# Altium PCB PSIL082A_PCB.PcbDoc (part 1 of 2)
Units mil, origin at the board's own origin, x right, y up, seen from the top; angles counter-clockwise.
Board outline 3500 x 2700 mil, 4 copper layers (Top Layer, Signal Layer 1, Signal Layer 2, Bottom Layer), stack 61.2 mil thick; 62 components, 57 nets, 283 pads, 94 vias.
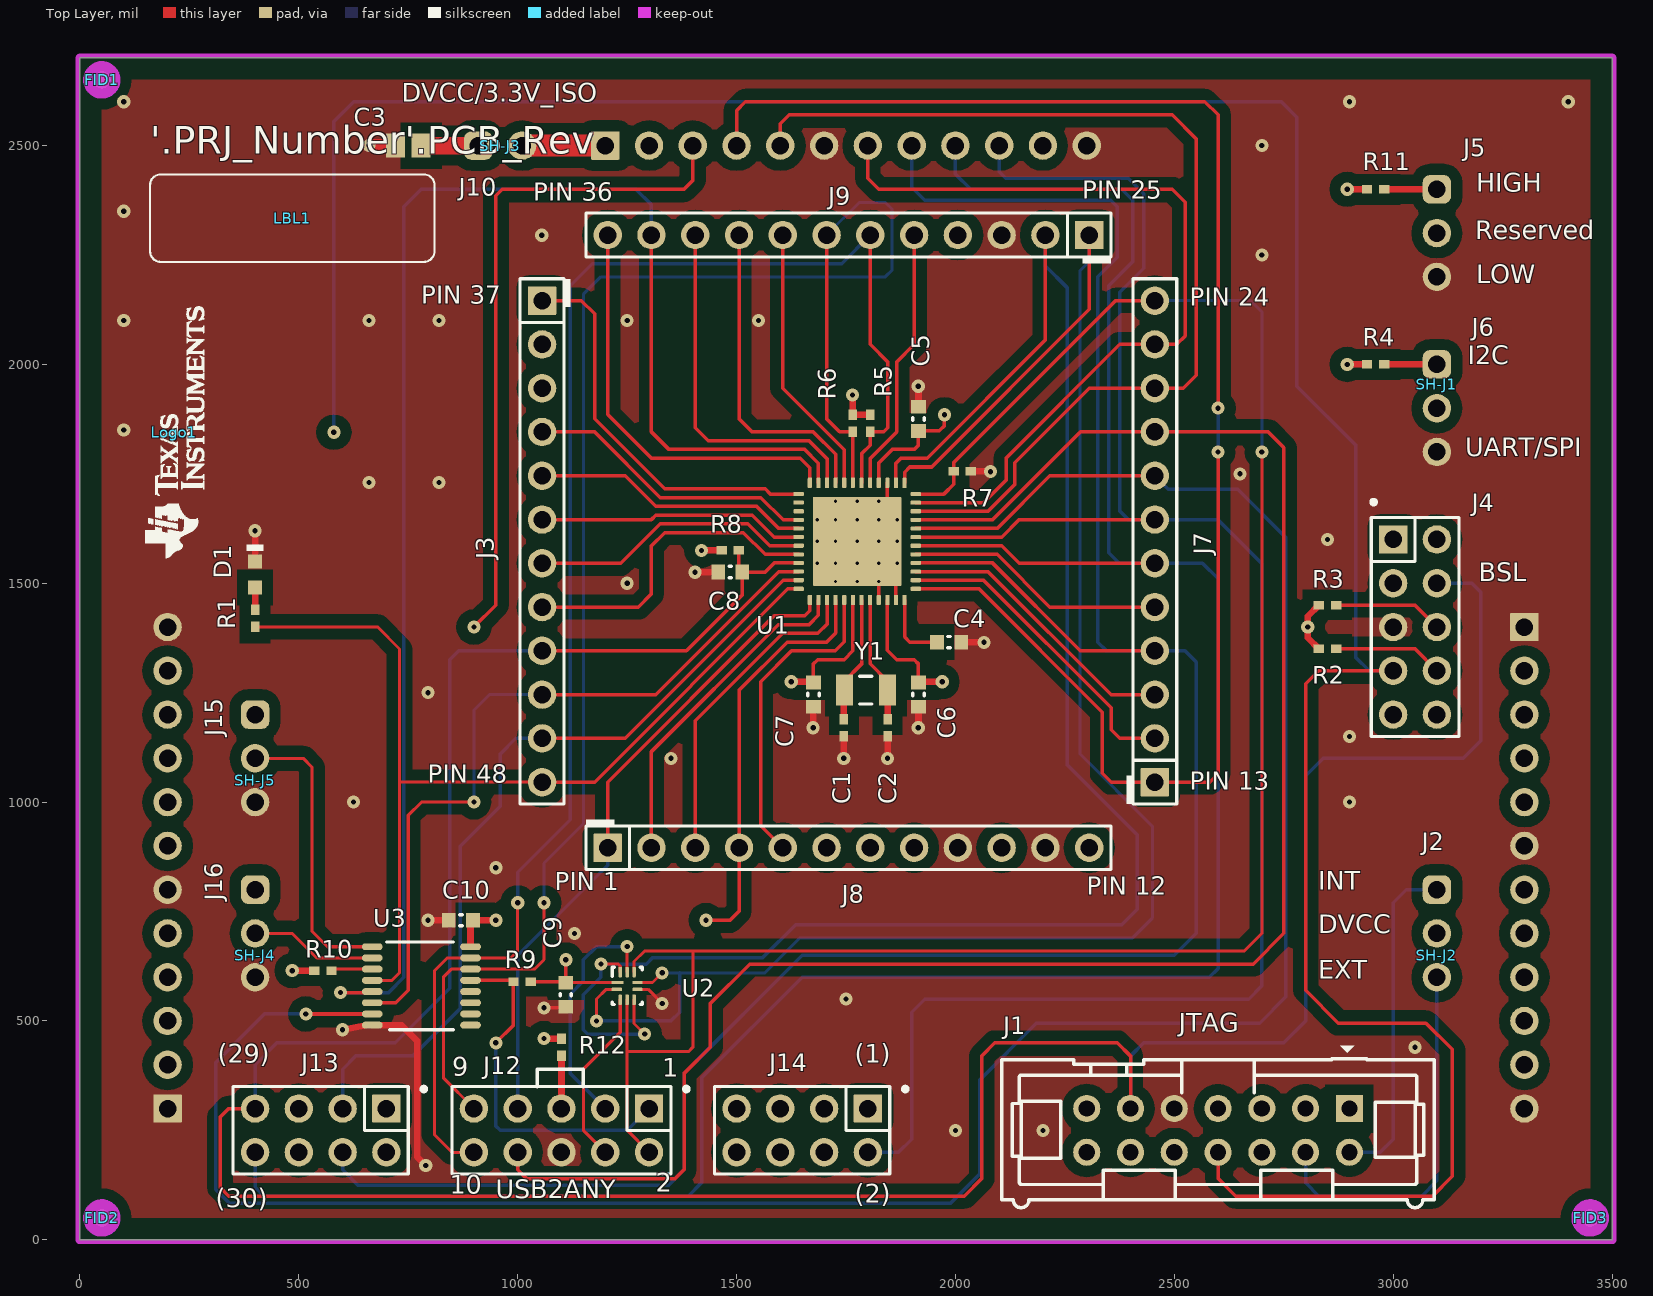
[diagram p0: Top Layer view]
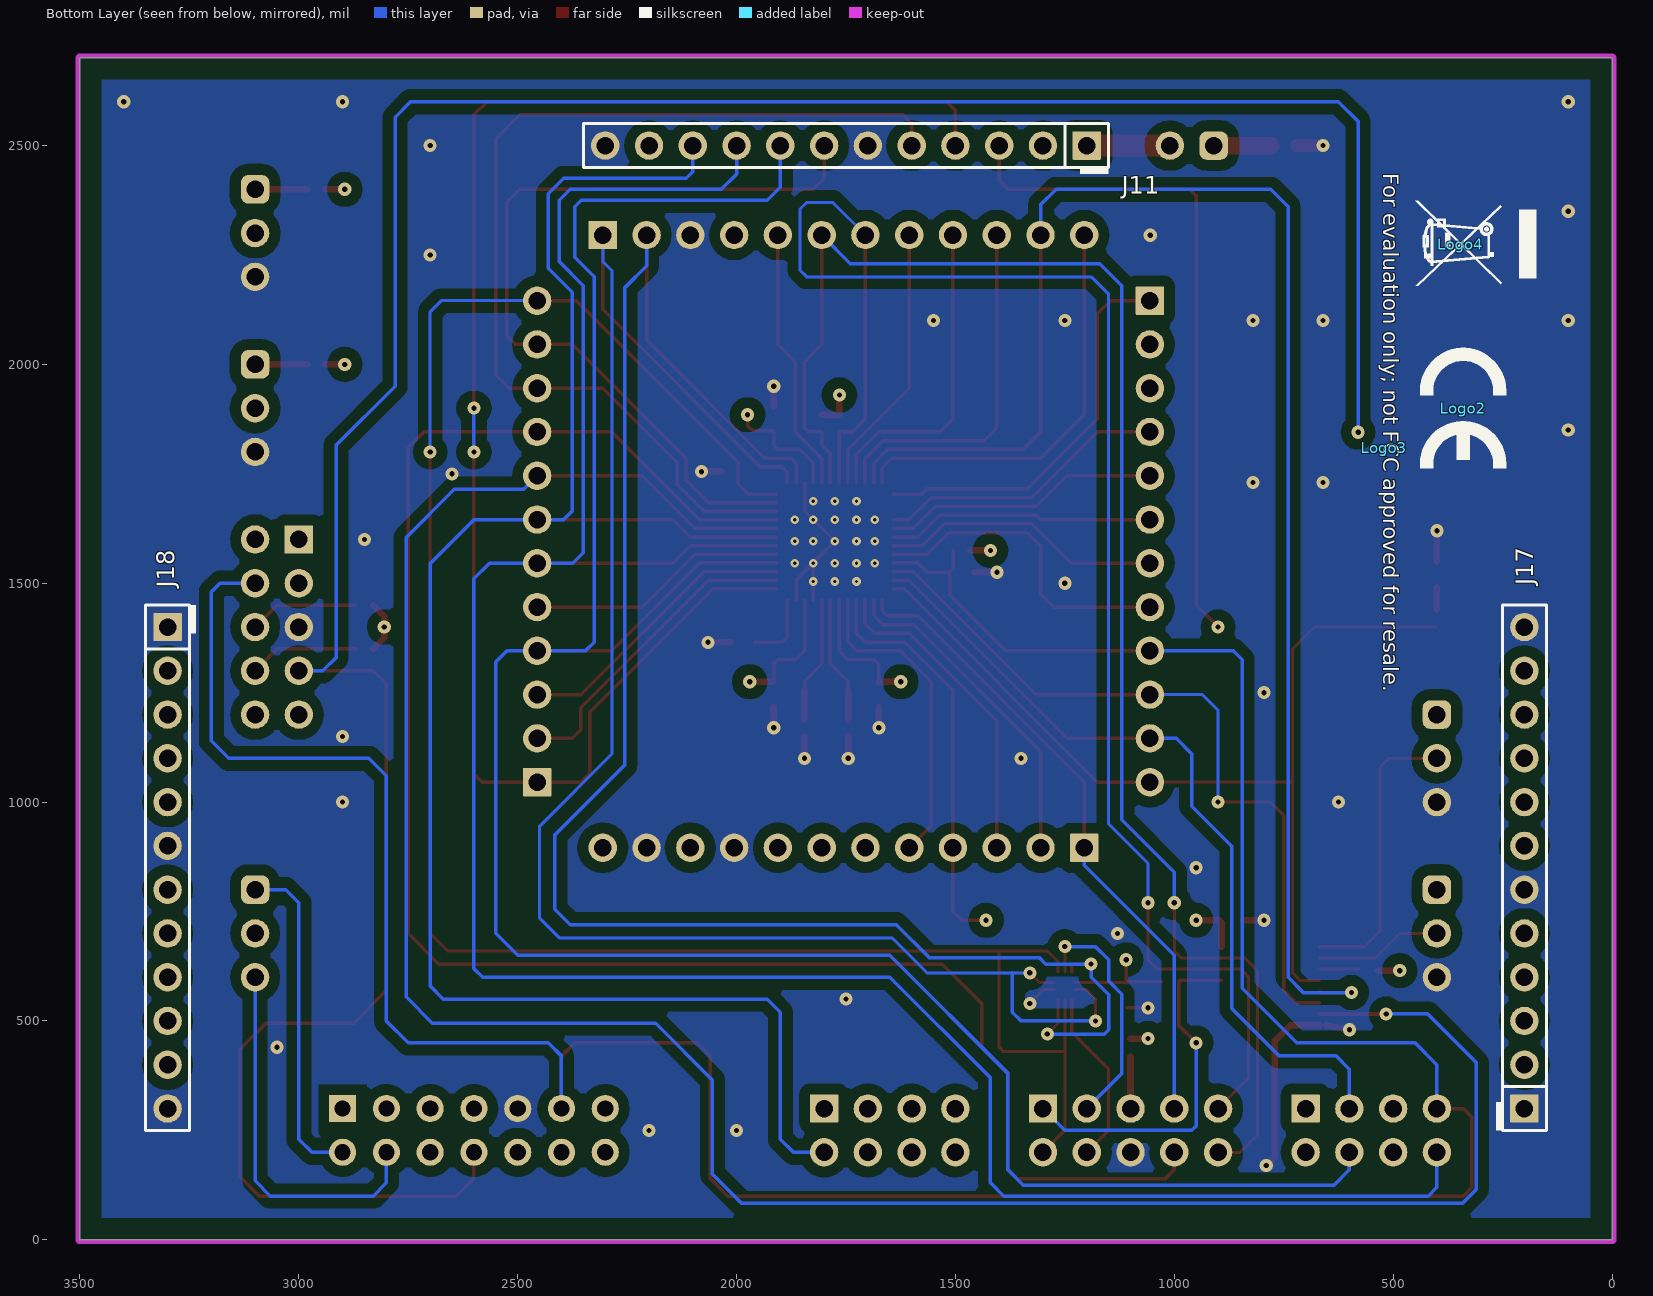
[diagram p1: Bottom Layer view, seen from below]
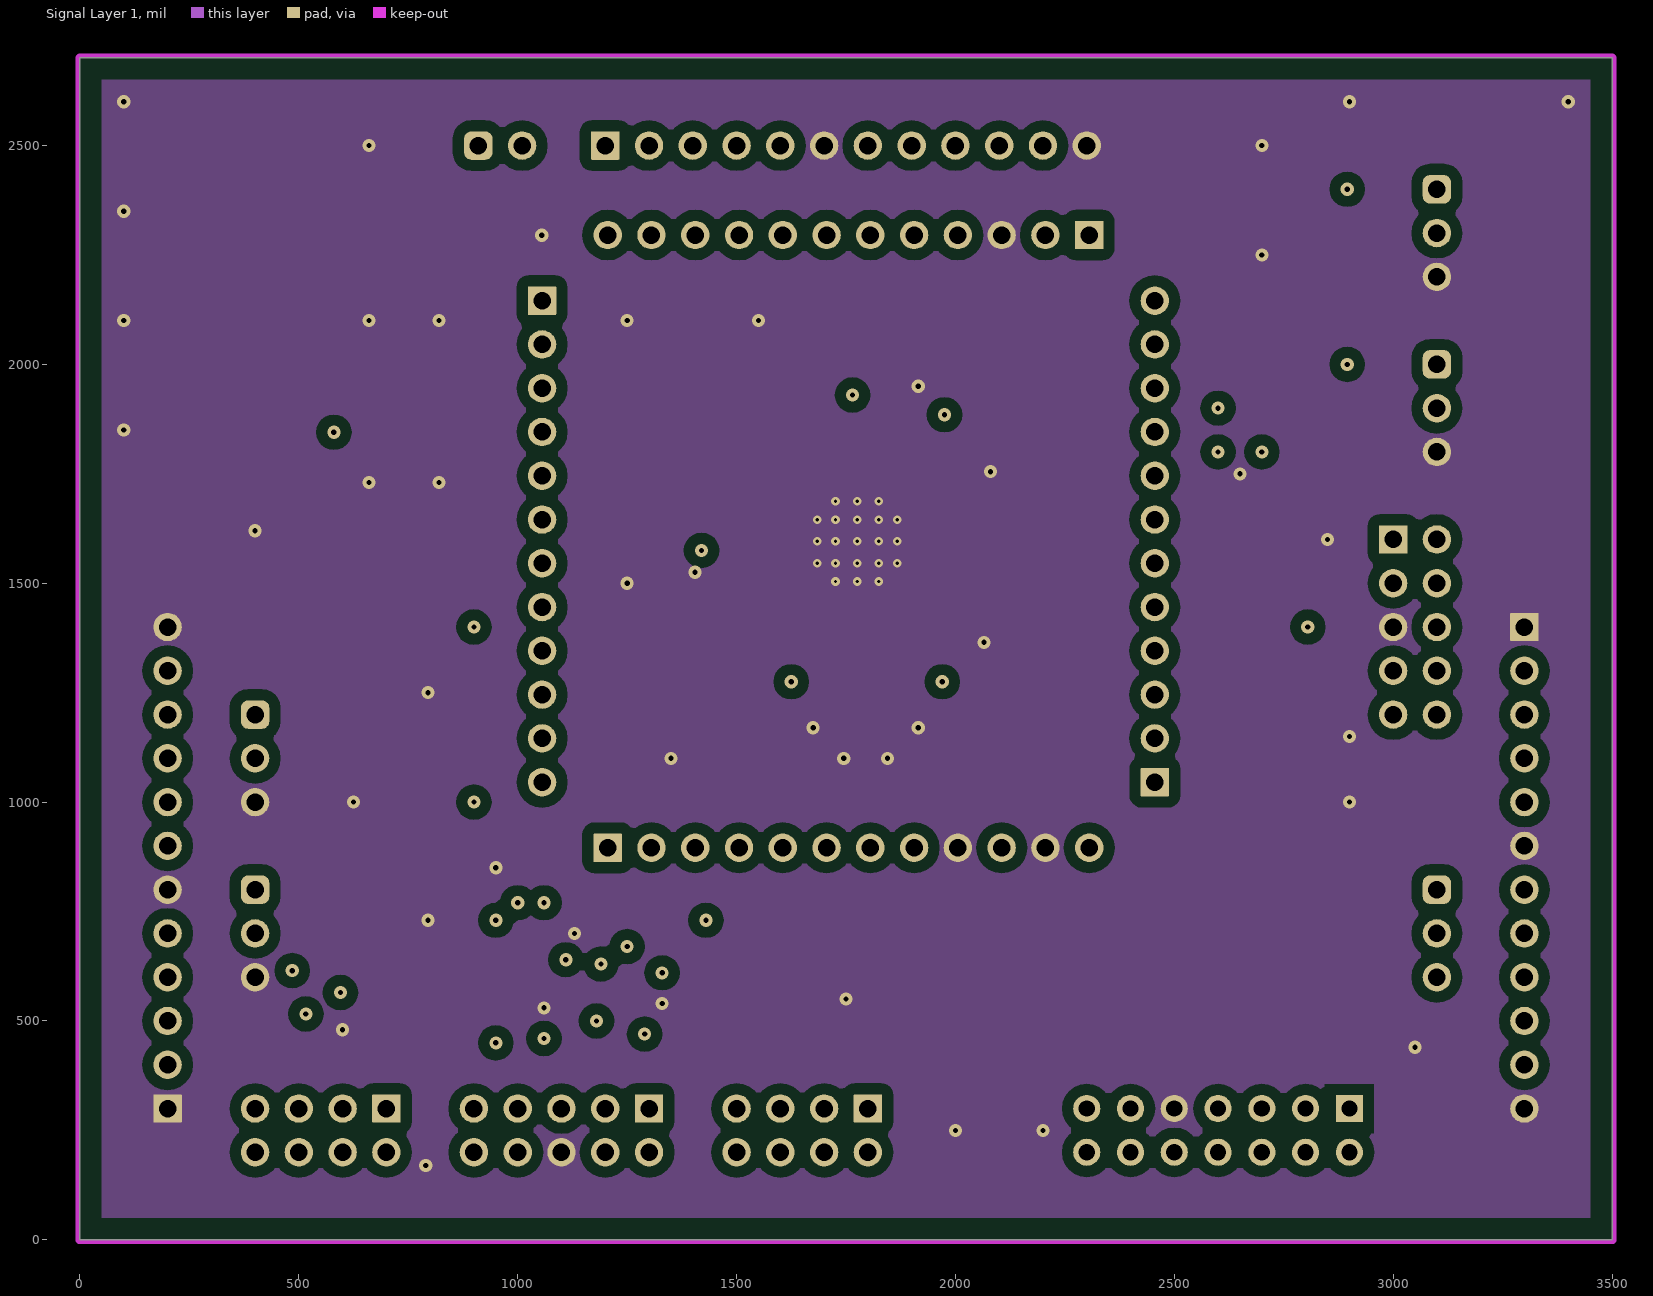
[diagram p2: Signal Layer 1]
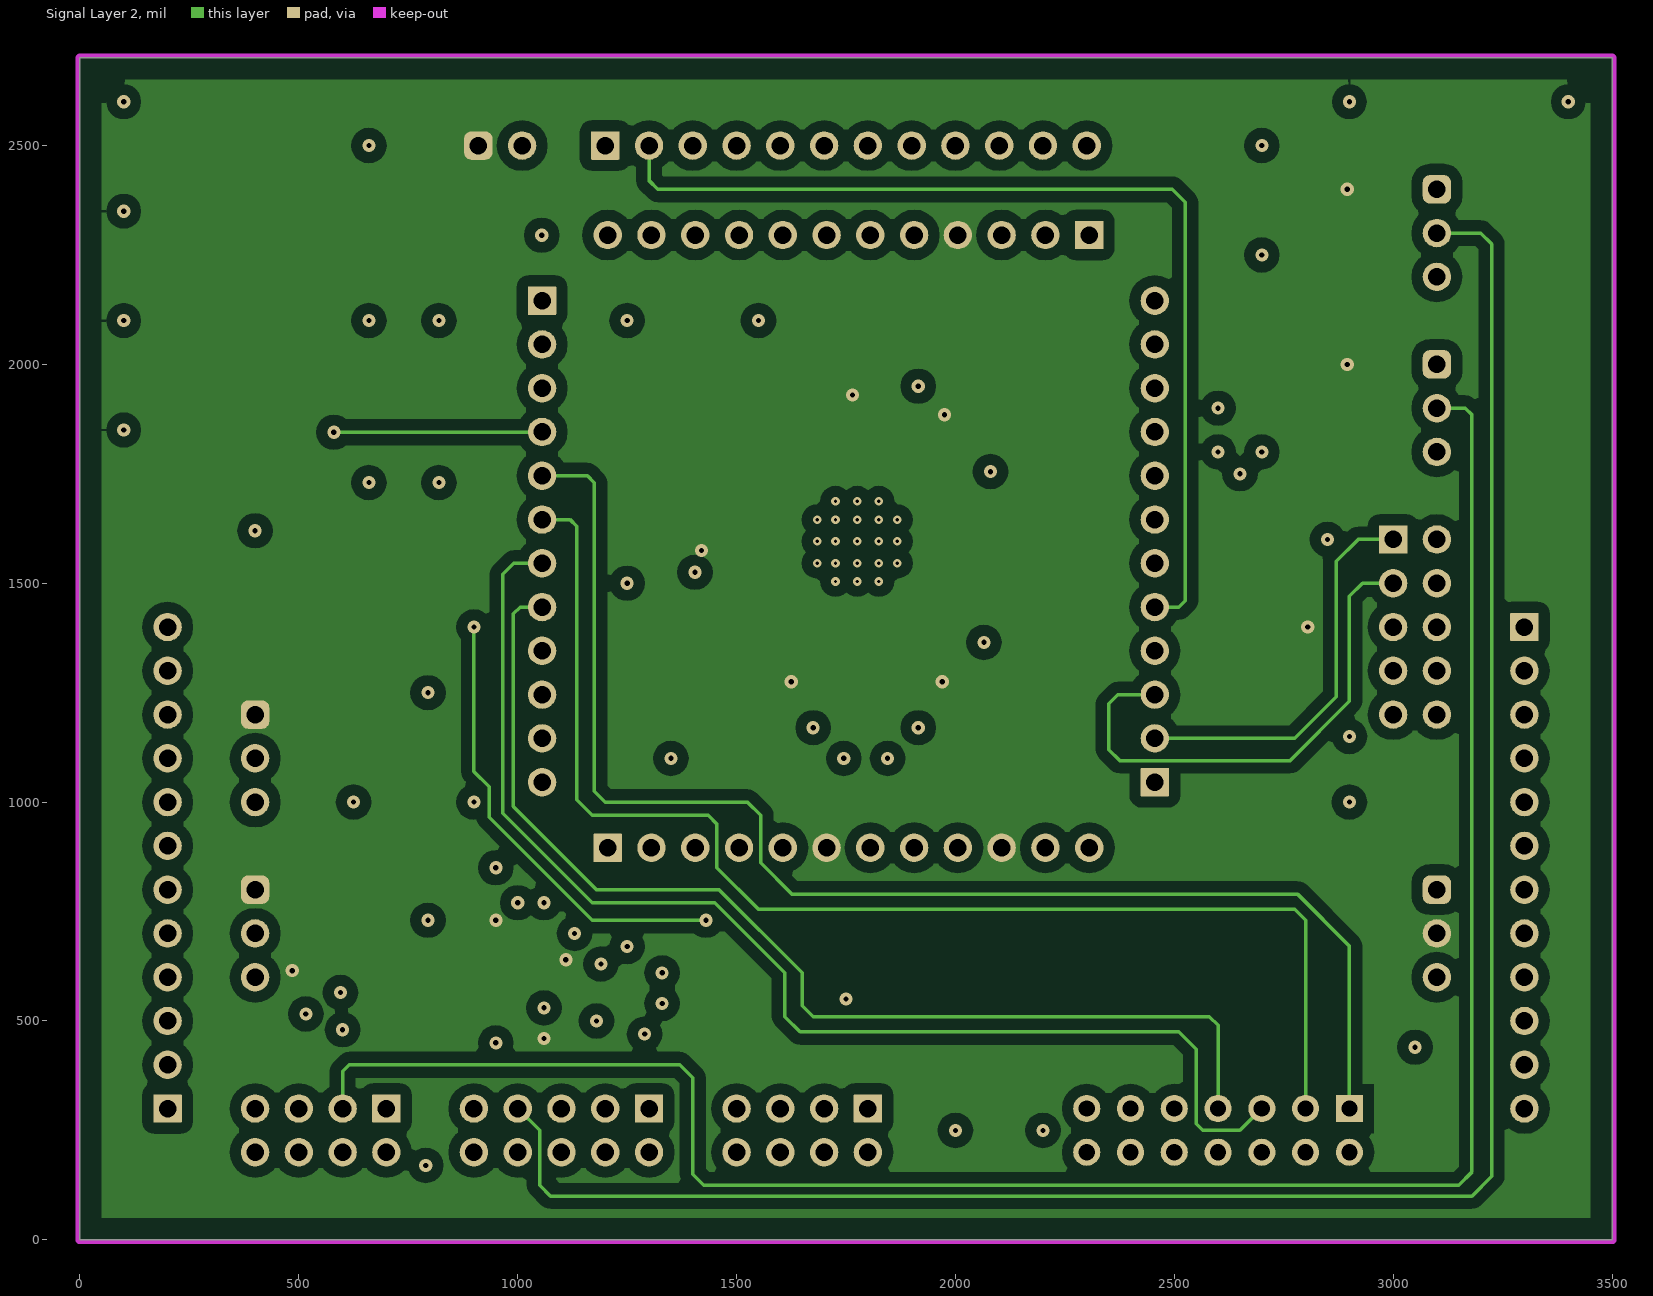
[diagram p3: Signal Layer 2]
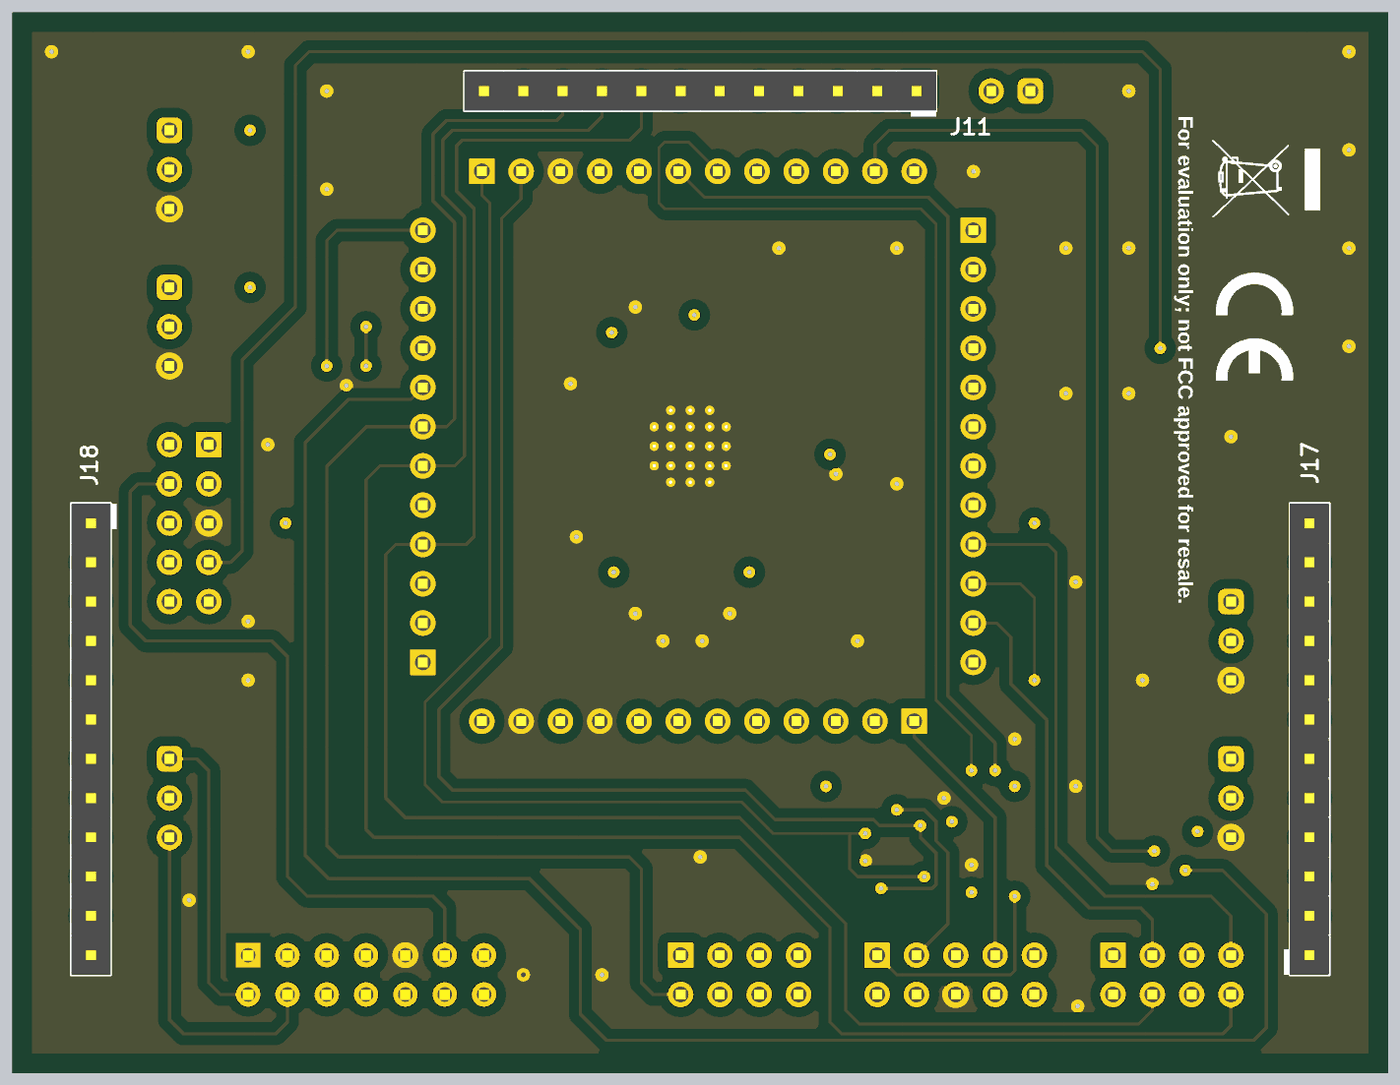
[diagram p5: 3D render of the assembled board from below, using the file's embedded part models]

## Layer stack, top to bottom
Top Solder: solder mask 0.4, Solder Resist, Dk 3.5
Top Layer: signal copper 1.4
Dielectric 2: core 20, FR-4, Dk 4.2
Signal Layer 1: signal copper 1.4
Dielectric1: prepreg 15.6, FR-4, Dk 4.2
Signal Layer 2: signal copper 1.4
Dielectric 3: core 20, FR-4, Dk 4.2
Bottom Layer: signal copper 1.4
Bottom Solder: solder mask 0.4, Solder Resist, Dk 3.5

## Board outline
0,0 3500,0 3500,2700 0,2700

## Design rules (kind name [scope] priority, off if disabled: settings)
AcuteAngle [All] p1: minimum=4.50000000000000E+0001 checktracksonly=FALSE
AssemblyTestPointUsage [All] p1: valid=2
BoardOutlineClearance BoardOutlineClearance_MountingHoles [OnCopper and InComponentClass('Mounting Holes')] p1: gap=40 ignorepadtopadclearanceinfootprint=FALSE
BoardOutlineClearance BoardOutlineClearance_Poly [OnCopper and IsPoly] p2: gap=25 ignorepadtopadclearanceinfootprint=FALSE
BoardOutlineClearance [OnCopper and Not InComponentClass('Logo') and not InComponentClass('FiducialMark') and not InRegion(1000,500,4000,800) and not InPoly] p3: gap=75 ignorepadtopadclearanceinfootprint=FALSE
Clearance Clearance_Keepouts [((IsTrack Or IsArc) And Not InPoly) And IsFree and IsKeepOut vs ((IsTrack Or IsArc) And Not InPoly) And IsFree and IsKeepOut] p1: gap=0 ignorepadtopadclearanceinfootprint=FALSE
Clearance Clearance_Poly [InPolygon] p2: gap=25 ignorepadtopadclearanceinfootprint=FALSE except(0: Arc-Hole Track-Hole SMDPad-Hole THPad-Hole Via-Hole Fill-Hole Poly-Hole Region-Hole Text-Hole)
Clearance Clearance_FiducialMark [IsKeepOut and InComponentClass('FiducialMark') vs IsPad and InComponentClass('FiducialMark')] p3: gap=0 ignorepadtopadclearanceinfootprint=FALSE
Clearance [All] p4: gap=7.87 ignorepadtopadclearanceinfootprint=FALSE except(0: Arc-Hole Track-Hole SMDPad-Hole THPad-Hole Via-Hole Fill-Hole Poly-Hole Region-Hole Text-Hole)
ComponentClearance ComponentClearance_MountingHoles_FiducialMarks [InComponentClass('Mounting Holes') vs InComponentClass('FiducialMark')] p1: gap=50 collisioncheckmode=3 verticalgap=10 showdistances=FALSE
ComponentClearance ComponentClearance_Shunt [InComponentClass('Header') vs InComponentClass('Shunt')] p2: gap=0 collisioncheckmode=3 verticalgap=0 showdistances=FALSE
ComponentClearance ComponentClearance_Logo [InComponentClass('Logo')] p3: gap=50 collisioncheckmode=3 verticalgap=10 showdistances=FALSE
ComponentClearance ComponentClearance_ScrewToNut [(HasFootprint('NY PMS 440 0025 PH')) vs (HasFootprint('Keystone_1902C'))] p4: gap=5 collisioncheckmode=3 verticalgap=10 showdistances=FALSE
ComponentClearance ComponentClearance_MountingHoles [InComponentClass('Mounting Holes')] p5: gap=250 collisioncheckmode=3 verticalgap=100000 showdistances=FALSE
ComponentClearance ComponentClearance_SmallPassives [HasFootprint('0201*') or HasFootprint('0402*') or HasFootprint('0508') or HasFootprint('0603*') or HasFootprint('0612') or HasFootprint('0805*') or HasFootprint('0815*') or HasFootprint('0830*') or HasFootprint('1206*') or HasFootprint('1210*') or HasFootprint('1808*') or HasFootprint('1812*') or HasFootprint('1825*') or HasFootprint('2010*') or HasFootprint('2220*') or HasFootprint('2225*') or HasFootprint('2512*') or HasFootprint('2728*') or HasFootprint('3518*') vs HasFootprint('0201*') or HasFootprint('0402*') or HasFootprint('0508') or HasFootprint('0603*') or HasFootprint('0612') or HasFootprint('0805*') or HasFootprint('0815*') or HasFootprint('0830*') or HasFootprint('1206*') or HasFootprint('1210*') or HasFootprint('1808*') or HasFootprint('1812*') or HasFootprint('1825*') or HasFootprint('2010*') or HasFootprint('2220*') or HasFootprint('2225*') or HasFootprint('2512*') or HasFootprint('2728*') or HasFootprint('3518*')] p6: gap=14.96 collisioncheckmode=3 verticalgap=10 showdistances=FALSE
ComponentClearance ComponentClearance_THtoSMT [IsThruComponent vs IsSMTComponent] p7: gap=40 collisioncheckmode=3 verticalgap=30 showdistances=FALSE
ComponentClearance ComponentClearance_THtoTH [IsThruComponent vs IsThruComponent] p8: gap=30 collisioncheckmode=3 verticalgap=30 showdistances=FALSE
ComponentClearance [All] p9: gap=30 collisioncheckmode=3 verticalgap=10 showdistances=FALSE
DiffPairsRouting [All] p1: maxlimit=100 minlimit=10 mostfreqgap=10 toplayer_minwidth=15 toplayer_maxwidth=15 toplayer_prefwidth=15 midlayer1_minwidth=15 midlayer1_maxwidth=15 midlayer1_prefwidth=15 midlayer2_minwidth=15 midlayer2_maxwidth=15 midlayer2_prefwidth=15 bottomlayer_minwidth=15 bottomlayer_maxwidth=15 bottomlayer_prefwidth=15 maxuncoupledlength=1000
FabricationTestPointUsage TestPointUsage [All] p1: valid=2 allowmultiple=FALSE
FabricationTestpoint Testpoint [All] p1: side=3 testpointundercomponent=TRUE minsize=40 maxsize=100 preferedsize=60 minholesize=0 maxholesize=40 preferedholesize=32 testpointgrid=1 allowsidetop=TRUE allowsidebottom=TRUE usegrid=TRUE gridtolerance=0.01
FanoutControl Fanout_LCC [IsLCC] p1: bgadir=Out bgaviamode=Centered fanoutstyle=Auto fanoutdirection=Alternating viagrid=1 // Fanout_LCC (Default Rule)
FanoutControl Fanout_BGA [IsBGA] p2: bgadir=Out bgaviamode=Centered fanoutstyle=Auto fanoutdirection=Alternating viagrid=1 // Fanout_BGA (Default Rule)
FanoutControl Fanout_Default [All] p4: bgadir=Out bgaviamode=Centered fanoutstyle=Auto fanoutdirection=Alternating viagrid=1 // Fanout_Default (Default Rule)
FanoutControl Fanout_Small [(CompPinCount < 5)] p5: bgadir=Out bgaviamode=Centered fanoutstyle=Auto fanoutdirection=OutThenIn viagrid=1 // Fanout_Small (Default Rule)
HoleSize [All] p1: absolutevalues=TRUE maxlimit=251 minlimit=7.87 maxpercent=80.000 minpercent=20.000
MinimumAnnularRing MinimumAnnularRing_ThermalPadVias [IsVia and InAnyComponent] p1: minimumring=5.91
MinimumAnnularRing [All] p2: minimumring=8
MinimumSolderMaskSliver MinimumSolderMaskSliver_Logo [InComponentClass('Logo') vs InComponentClass('Logo')] p1: minsoldermaskwidth=0.7
MinimumSolderMaskSliver [All] p2: minsoldermaskwidth=3.94
PlaneConnect [All] p1: planeconnectstyle=Relief reliefexpansion=10 reliefentries=4 reliefconductorwidth=10 reliefairgap=10
PolygonConnect [All] p1: connectstyle=Direct reliefconductorwidth=10 reliefentries=4 polygonreliefangle="90 Angle" airgapwidth=10
RoutingVias ThermalPadVias [IsVia and InAnyComponent] p1: holewidth=7.87 width=19.68 viastyle="Through Hole" minholewidth=7.87 minwidth=19.68 maxholewidth=12.99 maxwidth=23.62
RoutingVias [All] p2: holewidth=12 width=30 viastyle="Through Hole" minholewidth=7.87 minwidth=26 maxholewidth=40 maxwidth=65
SilkToBoardRegionClearance [Not ((IsComment or IsDesignator) And (Hide <> 'False')) and not InRegion(1000,500,4000,800)] p1:
SilkToSilkClearance SilkToSilkClearance_Pb-FreeLogo [(HasFootprint('Pb-Free_Overlay_Medium') OR HasFootprint('Pb-Free_Overlay_Small')) vs (HasFootprint('Pb-Free_Overlay_Medium') OR HasFootprint('Pb-Free_Overlay_Small'))] p1: silktosilkclearance=0
SilkToSilkClearance [All] p2: silktosilkclearance=4
SilkToSolderMaskClearance SilkToComponentPadClearance [(IsPad or IsFill or IsRegion) and InAnycomponent] p1: minsilkscreentomaskgap=5 clearancetoexposedcopper=TRUE
SilkToSolderMaskClearance "Silk to Solder Mask Opening" [All] p2: minsilkscreentomaskgap=4 clearancetoexposedcopper=FALSE
SolderMaskExpansion [All] p1: expansion=1.97
Width [All] p1: maxlimit=100 minlimit=6 preferedwidth=10 checkconnectedcopper=TRUE
15 further rules are at their usual default settings.

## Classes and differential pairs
component class PSIL082A_SH1: C1 C2 C3 C4 C5 C6 C7 C8 C9 C10 D1 J1 J2 J3 J4 J5 J6 J7 J8 J9 J10 J11 J12 J13 J14 J15 J16 J17 J18 R1 R2 R3 R4 R5 R6 R7 R8 R9 R10 R11 R12 U1 U2 U3 Y1
component class Header: J1 J2 J3 J4 J5 J6 J7 J8 J9 J10 J11 J12 J13 J14 J15 J16 J17 J18
component class AssemblyNote: ZZ1 ZZ2 ZZ3 ZZ4
component class FiducialMark: FID1 FID2 FID3
component class Label: LBL1
component class Logo: Logo1
component class PSIL082A_EVM_Hardware: !PCB FID1 FID2 FID3 LBL1 Logo1 Logo2 Logo3 Logo4 SH-J1 SH-J2 SH-J3 SH-J4 SH-J5 ZZ1 ZZ2 ZZ3 ZZ4
component class Shunt: SH-J1 SH-J2 SH-J3 SH-J4 SH-J5

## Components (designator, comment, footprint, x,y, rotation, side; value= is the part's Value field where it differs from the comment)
C1 "CL05C120JB5NNNC" 0402L 1745,1170 r90 top value=12pF
C2 "CL05C120JB5NNNC" 0402L 1845,1170 r90 top value=12pF
C3 "885012207026" 0805L 750,2500 r0 top value=10uF
C4 "GCM188R71C474KA55D" 0603L 1985.59,1365.59 r180 top value=0.47uF
C5 "885012206046" 0603L 1915.59,1875.59 r270 top value=0.1uF
C6 "885012206046" 0603L 1915.59,1245.59 r90 top value=0.1uF
C7 "885012206046" 0603L 1675.59,1245.59 r90 top value=0.1uF
C8 "885012206083" 0603L 1485.59,1525.59 r180 top value=1000pF
C9 "885012206046" 0603L 1110,560 r90 top value=0.1uF
C10 "885012206046" 0603L 870,730 r0 top value=0.1uF
D1 "LTST-C190KGKT" LED_LTST-C190_G 400,1520 r90 top value=Green
FID1 "Fiducial" Fiducial10-20 50,2650 r90 top
FID2 "Fiducial" Fiducial10-20 50,50 r90 top
FID3 "Fiducial" Fiducial10-20 3450,50 r90 top
J1 "N2514-6002-RB" 3M_x2514-60xx 2600,250 r180 top
J2 "TSW-103-07-G-S" TSW-103-07-G-S 3100,700 r270 top
J3 "TSW-112-07-G-S" TSW-112-07-G-S 1055.59,1595.59 r270 top
J4 "TSW-105-07-G-D" TSW-105-07-G-D 3050,1400 r270 top
J5 "TSW-103-07-G-S" TSW-103-07-G-S 3100,2300 r270 top
J6 "TSW-103-07-G-S" TSW-103-07-G-S 3100,1900 r270 top
J7 "TSW-112-07-G-S" TSW-112-07-G-S 2455.59,1595.59 r90 top
J8 "TSW-112-07-G-S" TSW-112-07-G-S 1755.59,895.59 r0 top
J9 "TSW-112-07-G-S" TSW-112-07-G-S 1755.59,2295.59 r180 top
J10 "TSW-102-07-G-S" TSW-102-07-G-S 960,2500 r0 top
J11 "TSW-112-07-G-S" TSW-112-07-G-S 1750,2500 r0 bottom
J12 "TSW-105-07-G-D" TSW-105-07-G-D 1100,250 r180 top
J13 "TSW-104-07-G-D" TSW-104-07-G-D 550,250 r180 top
J14 "TSW-104-07-G-D" TSW-104-07-G-D 1650,250 r180 top
J15 "TSW-103-07-G-S" TSW-103-07-G-S 400,1100 r270 top
J16 "TSW-103-07-G-S" TSW-103-07-G-S 400,700 r270 top
J17 "TSW-112-07-G-S" TSW-112-07-G-S 200,850 r90 bottom
J18 "TSW-112-07-G-S" TSW-112-07-G-S 3300,850 r270 bottom
LBL1 "THT-14-423-10" Label_650x200 485,2334.03 r180 top
Logo1 "Texas Instruments" TI_Stacked_Overlay_Small_Vertical 215,1845 r0 top
Logo2 "CE Mark" CE_Mark_5mm 340,1900 r270 bottom (schematic designator LOGO2)
Logo3 "FCC disclaimer" FCC_disclaimer 520.07,1810 r270 bottom
Logo4 "WEEE logo" WEEE_Minimum 345,2275 r90 bottom
R1 "CRCW0402330RJNED" 0402L 400,1420 r90 top value=330
R2 "ERJ-2GE0R00X" 0402L 2850,1350 r0 top value=0
R3 "ERJ-2GE0R00X" 0402L 2850,1450 r0 top value=0
R4 "CRCW040247K0JNED" 0402L 2960,2000 r180 top value=47k
R5 "CRCW040247K0JNED" 0402L 1805.59,1865.59 r90 top value=47k
R6 "CRCW040247K0JNED" 0402L 1765.59,1865.59 r90 top value=47k
R7 "CRCW04022M00FKED" 0402L 2015.59,1755.59 r0 top value=2.00Meg
R8 "CRCW040247K0JNED" 0402L 1485.59,1575.59 r0 top value=47k
R9 "CRCW040247K0JNED" 0402L 1010,590 r0 top value=47k
R10 "CRCW040247K0JNED" 0402L 555,615 r180 top value=47k
R11 "CRCW040247K0JNED" 0402L 2960,2400 r180 top value=47k
R12 "ERJ-2GE0R00X" 0402L 1100,440 r270 top value=0
SH-J1 "SPC02SYAN" SPC02SYAN 3100,1955 r90 top value=1x2
SH-J2 "SPC02SYAN" SPC02SYAN 3100,650 r90 top value=1x2
SH-J3 "SPC02SYAN" SPC02SYAN 960,2500 r180 top value=1x2
SH-J4 "SPC02SYAN" SPC02SYAN 400,650 r90 top value=1x2
SH-J5 "SPC02SYAN" SPC02SYAN 400,1050 r90 top value=1x2
U1 "MSP430F5234IRGZR" RGZ0048A 1775.59,1595.59 r90 top
U2 "TS3A5223RSWR" RSW0010A 1250,580 r0 top
U3 "PCA9538PWR" PW0016A_L 780,580 r0 top
Y1 "FC-135 32.7680KA-AG0" Epson_FC-135 1795.59,1255.59 r0 top
ZZ1 "This Assembly Note is for PCB labels only" AssemblyNoteLabel 195,4115 r0 top
ZZ2 "These assemblies are ESD sensitive, ESD precautions shall be observed." AssemblyNote 185,3965 r0 top
ZZ3 "These assemblies must be clean and free from flux and all contaminants. Use of no clean flux is not acceptable." AssemblyNote 175,3815 r0 top
ZZ4 "These assemblies must comply with workmanship standards IPC-A-610 Class 2, unless otherwise specified." AssemblyNote 185,3620 r0 top

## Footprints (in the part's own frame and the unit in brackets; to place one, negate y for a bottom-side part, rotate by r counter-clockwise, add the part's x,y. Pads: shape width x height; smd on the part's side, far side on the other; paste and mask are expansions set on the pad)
3M_x2514-60xx [mil] "3M"
  rect 62x62 hole 37 paste+2: 1(-300,-50)
  round 62 hole 37: 2(-300,50) 3(-200,-50) 4(-200,50) 5(-100,-50) 6(-100,50) 7(0,-50) 8(0,50) 9(100,-50) 10(100,50) 11(200,-50) 12(200,50) 13(300,-50) 14(300,50)
  silkscreen extent -494,-193 494,177, body extent -494,-161 494,179, height 390
0402L [mm] "0402 from SM-752 data"
  rect 0.6x0.5 smd: 1(-0.5,0) 2(0.5,0)
  body extent -0.55,-0.3 0.55,0.3, height 0.6
0603L [mm] "0603 from SM-752 data"
  rect 0.8x0.85 smd: 1(-0.7,0) 2(0.7,0)
  silkscreen extent -0.07,-0.33 0.07,0.33, body extent -0.87,-0.47 0.87,0.47, height 1
0805L [mm] "0805 from SM-752 data"
  rect 1.1x1.4 smd: 1(-0.75,0) 2(0.75,0)
  body extent -1.1,-0.72 1.1,0.72, height 1.45
AssemblyNote [mil] "Assembly Note"
AssemblyNoteLabel [mil] "Assembly Note for PCB Labels"
CE_Mark_5mm [mil] "Minimum text height for CE Mark"
  silkscreen extent -138,-98 138,98
Epson_FC-135 [mm] "SMD, 2-Leads, Body 3.2x1.5mm"
  rect 1x1.8 smd: 1(-1.25,0) 2(1.25,0)
  silkscreen extent -0.35,-0.8 0.35,0.8, body extent -1.65,-0.8 1.65,0.8, height 0.9
FCC_disclaimer [mil]
Fiducial10-20 [mm]
  round 1 smd mask+0.5: 1(0,0)
  Top Layer keep-out circle w1.178: c0,0 r0.5
Label_650x200 [mil] "Thermal Transfer Label"
  round 1 on Mech13: 0(0,0)
  silkscreen extent -325,-100 325,100, body extent -325,-100 325,100, height 1
LED_LTST-C190_G [mm] "Lite-On"
  rect 0.8x0.8 smd: 1(-0.75,0) 2(0.75,0)
  silkscreen extent 1.37,-0.5 1.75,0.5, body extent -0.85,-0.45 0.85,0.45, height 0.9
PW0016A_L [mm] "TSOP, 16-Leads, Body 5x4.4mm, Pitch 0.65mm, IPC High Density"
  oval 1.2x0.4 smd: 1(-2.85,2.275) 2(-2.85,1.625) 3(-2.85,0.975) 4(-2.85,0.325) 5(-2.85,-0.325) 6(-2.85,-0.975) 7(-2.85,-1.625) 8(-2.85,-2.275) 9(2.85,-2.275) 10(2.85,-1.625) 11(2.85,-0.975) 12(2.85,-0.325) 13(2.85,0.325) 14(2.85,0.975) 15(2.85,1.625) 16(2.85,2.275)
  silkscreen extent -2,-2.55 1.85,2.55, body extent -3.21,-2.5 3.21,2.5, height 1
RGZ0048A [mm] "VQFN-48"
  rrect42% 0.6x0.24 smd: 1(-3.4,2.75) 2(-3.4,2.25) 3(-3.4,1.75) 4(-3.4,1.25) 5(-3.4,0.75) 6(-3.4,0.25) 7(-3.4,-0.25) 8(-3.4,-0.75) 9(-3.4,-1.25) 10(-3.4,-1.75) 11(-3.4,-2.25) 12(-3.4,-2.75) 25(3.4,-2.75) 26(3.4,-2.25) 27(3.4,-1.75) 28(3.4,-1.25) 29(3.4,-0.75) 30(3.4,-0.25) 31(3.4,0.25) 32(3.4,0.75) 33(3.4,1.25) 34(3.4,1.75) 35(3.4,2.25) 36(3.4,2.75)
  rrect42% 0.24x0.6 smd: 13(-2.75,-3.4) 14(-2.25,-3.4) 15(-1.75,-3.4) 16(-1.25,-3.4) 17(-0.75,-3.4) 18(-0.25,-3.4) 19(0.25,-3.4) 20(0.75,-3.4) 21(1.25,-3.4) 22(1.75,-3.4) 23(2.25,-3.4) 24(2.75,-3.4) 37(2.75,3.4) 38(2.25,3.4) 39(1.75,3.4) 40(1.25,3.4) 41(0.75,3.4) 42(0.25,3.4) 43(-0.25,3.4) 44(-0.75,3.4) 45(-1.25,3.4) 46(-1.75,3.4) 47(-2.25,3.4) 48(-2.75,3.4)
  rrect2% 5.15x5.15 smd paste-2.6: 49(0,0)
  body extent -3.5,-3.5 3.5,3.5, height 1
RSW0010A [mm] "QFN, 10-Leads, Body 1.8x1.4 mm, Pitch 0.4mm, TI Recommended"
  rrect50% 0.7x0.2 smd: 1(-0.55,0.2)
  rrect50% 0.6x0.2 smd: 2(-0.6,-0.2) 6(0.6,-0.2) 7(0.6,0.2)
  rrect50% 0.2x0.6 smd: 3(-0.4,-0.8) 4(0,-0.8) 5(0.4,-0.8) 8(0.4,0.8) 9(0,0.8) 10(-0.4,0.8)
  silkscreen extent -0.88,-1.08 0.88,1.08, body extent -0.7,-0.9 0.7,0.9, height 0.56
SPC02SYAN [mil] "SULLINS"
  round 1 on Mech3: 0(0,0)
  body extent -98,-47 99,47, height 366
TI_Stacked_Overlay_Small_Vertical [mil]
  silkscreen extent -66,-288 69,288
TSW-102-07-G-S [mm] "Samtec 100mil, 1x2, 230 mil above insulator"
  rrect50% 1.65x1.65 hole 1.016: 1(-1.27,0)
  round 1.65 hole 1.016: 2(1.27,0)
  body extent -2.54,-1.27 2.54,1.27, height 8.38
TSW-103-07-G-S [mm] "Samtec 100mil, 1x3, 230 mil above insulator"
  rrect50% 1.65x1.65 hole 1.016: 1(-2.54,0)
  round 1.65 hole 1.016: 2(0,0) 3(2.54,0)
  body extent -3.81,-1.27 3.81,1.27, height 8.38
TSW-104-07-G-D [mm] "Samtec 100mil, 2x4, 230 mil above insulator"
  rrect6% 1.65x1.65 hole 1.016: 1(-3.81,-1.27)
  round 1.65 hole 1.016: 2(-3.81,1.27) 3(-1.27,-1.27) 4(-1.27,1.27) 5(1.27,-1.27) 6(1.27,1.27) 7(3.81,-1.27) 8(3.81,1.27)
  silkscreen extent -6.11,-2.54 5.08,2.54, body extent -5.08,-2.54 5.08,2.54, height 8.38
TSW-105-07-G-D [mm] "Samtec 100mil, 2x5, 230 mil above insulator"
  rrect6% 1.65x1.65 hole 1.016: 1(-5.08,-1.27)
  round 1.65 hole 1.016: 2(-5.08,1.27) 3(-2.54,-1.27) 4(-2.54,1.27) 5(0,-1.27) 6(0,1.27) 7(2.54,-1.27) 8(2.54,1.27) 9(5.08,-1.27) 10(5.08,1.27)
  silkscreen extent -7.37,-2.54 6.35,2.54, body extent -6.35,-2.54 6.35,2.54, height 8.38
TSW-112-07-G-S [mm] "Samtec 100mil, 1x12, 230 mil above insulator"
  rrect6% 1.65x1.65 hole 1.016 mask+0: 1(-13.97,0)
  round 1.65 hole 1.016 mask+0: 2(-11.43,0) 3(-8.89,0) 4(-6.35,0) 5(-3.81,0) 6(-1.27,0) 7(1.27,0) 8(3.81,0) 9(6.35,0) 10(8.89,0) 11(11.43,0) 12(13.97,0)
  silkscreen extent -15.24,-1.27 15.24,1.65, body extent -15.24,-1.27 15.24,1.27, height 8.38
WEEE_Minimum [mil] "WEEElie bin"
  silkscreen extent -95,-172 99,104

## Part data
C1 C2: library part CMP-0006345-2, "CAP, CERM, 12 pF, 50 V, +/- 5%, C0G/NP0, 0402", Cap_Case=0402, Manufacturer="Samsung Electro-Mechanics", Supplier Part Number 1=1276-1178-1-ND, TempCo=C0G/NP0, Tolerance_%=5%, Value1=Unknown, Value2=50V, ValueDisplayed=12pF
C3: library part CMP-0007691-2, "CAP, CERM, 10 uF, 10 V, +/- 10%, X7R, 0805", Cap_Case=0805, Manufacturer="Wurth Elektronik", Supplier Part Number 1=710-885012207026, TempCo=X7R, Tolerance_%=10%, Value1=Unknown, Value2=10V, ValueDisplayed=10uF
C4: library part CMP-0007138-4, "CAP, CERM, 0.47 uF, 16 V, +/- 10%, X7R, AEC-Q200 Grade 1, 0603", Cap_Case=0603, Manufacturer=MuRata, Supplier Part Number 1=490-4775-1-ND, TempCo=X7R, Tolerance_%=10%, Value1=Unknown, Value2=16V, ValueDisplayed=0.47uF
C5 C6 C7 C9 C10: library part CMP-0006829-4, "CAP, CERM, 0.1 uF, 16 V, +/- 10%, X7R, 0603", Cap_Case=0603, Manufacturer="Wurth Elektronik", Supplier Part Number 1=710-885012206046, TempCo=X7R, Tolerance_%=10%, Value1=Unknown, Value2=16V, ValueDisplayed=0.1uF
C8: library part CMP-0064933-4, "CAP, CERM, 1000 pF, 50 V,+/- 10%, X7R, 0603", Cap_Case=0603, Manufacturer="Wurth Elektronik", Supplier Part Number 1=732-8001-1-ND, TempCo=X7R, Tolerance_%=10%, Value1=Unknown, Value2=50V, ValueDisplayed=1000pF
D1: library part CMP-0002840-2, "LED, Green, SMD", Color=green, Manufacturer=Lite-On, Value1=W, Value2=2V
FID1 FID2 FID3: library part CMP-0077181-1, "Fiducial mark.  There is nothing to buy or mount.", Manufacturer=N/A
J1: library part CMP-0075023-2, "Header (shrouded), 100mil, 7x2, Gold, TH", Manufacturer=3M, Supplier Part Number 1=MHC14K-ND
J2 J5 J6 J15 J16: library part CMP-0075407-2, "Header, 100mil, 3x1, Gold, TH", Color=Black, Current_A=6.3A, Manufacturer=Samtec, Supplier Part Number 1=SAM1029-03-ND, Voltage_V=550V
J3 J7 J8 J9 J11 J17 J18: library part CMP-0075424-1, "Header, 100mil, 12x1, Gold, TH", Color=Black, Current_A=6.3A, Manufacturer=Samtec, Supplier Part Number 1=SAM1029-12-ND, Voltage_V=550V
J4 J12: library part CMP-0075410-2, "Header, 100mil, 5x2, Gold, TH", Color=Black, Current_A=6.3A, Manufacturer=Samtec, Supplier Part Number 1=SAM1028-05-ND, Voltage_V=550V
J10: library part CMP-0075405-2, "Header, 100mil, 2x1, Gold, TH", Color=Black, Current_A=6.3A, Manufacturer=Samtec, Supplier Part Number 1=SAM1029-02-ND, Voltage_V=550V
J13 J14: library part CMP-0075408-2, "Header, 100mil, 4x2, Gold, TH", Color=Black, Current_A=6.3A, Manufacturer=Samtec, Supplier Part Number 1=SAM1028-04-ND, Voltage_V=550V
LBL1: library part CMP-0003625-1, "Thermal Transfer Printable Labels, 0.650\" W x 0.200\" H - 10,000 per roll", Manufacturer=Brady, Supplier Part Number 1=97C5133
Logo1: library part CMP-0074838-1, "Texas Instrument Corporate Signature"
Logo2: library part CMP-0074844-1
Logo3: library part CMP-0074847-1, "FCC_disclaimer"
Logo4: library part CMP-0074769-1
R1: library part CMP-0026906-3, "RES, 330, 5%, 0.063 W, AEC-Q200 Grade 0, 0402", Manufacturer=Vishay-Dale, Power_W=63mW, Supplier Part Number 1=541-330JCT-ND, TempCo="200 ppm/C", Tolerance_%=5%, Value2=0.063W, Value_Code=330R, ValueDisplayed=330
R2 R3 R12: library part CMP-0026992-3, "RES, 0, 5%, 0.1 W, AEC-Q200 Grade 0, 0402", Manufacturer=Panasonic, Power_W=100mW, Supplier Part Number 1=P0.0JCT-ND, TempCo="600 ppm/C", Tolerance_%=5%, Value2=0.1W, Value_Code=0000, ValueDisplayed=0
R4 R5 R6 R8 R9 R10 R11: library part CMP-0026935-3, "RES, 47 k, 5%, 0.063 W, AEC-Q200 Grade 0, 0402", Manufacturer=Vishay-Dale, Power_W=63mW, Supplier Part Number 1=541-47KJCT-ND, TempCo="200 ppm/C", Tolerance_%=5%, Value2=0.063W, Value_Code=47k0, ValueDisplayed=47k
R7: library part CMP-0026245-2, "RES, 2.00 M, 1%, 0.063 W, AEC-Q200 Grade 0, 0402", Manufacturer=Vishay-Dale, Power_W=63mW, Supplier Part Number 1=541-2.00MLCT-ND, TempCo="100 ppm/C", Tolerance_%=1%, Value2=0.063W, Value_Code=2M00, ValueDisplayed=2.00M
SH-J1 SH-J2 SH-J3 SH-J4 SH-J5: library part CMP-0003642-1, "Shunt, 100mil, Flash Gold, Black", Manufacturer="Sullins Connector Solutions", Supplier Part Number 1=S9001-ND
U1: library part CMP-0076591-3, "Ultra-Low Power MSP430 with 128 KB Flash, RGZ0048A (VQFN-48)", Alternate Manufacturer="Texas Instruments", Alternate PartNumber=MSP430F5234IRGZT, Operating Temperature Range="-40 to 85 C", Rating=Catalog
U2: library part CMP-0085520-1, "0.5? Dual SPDT Bidirectional Analog Switch, RSW0010A (UQFN-10)", Alternate Manufacturer="Texas Instruments", Operating Temperature Range="-40 to 85 C", Rating=Catalog
U3: library part CMP-0043202-2, "Remote 8-Bit I2C and SMBus Low-Power I/O Expander With Interrupt Output, Reset, and Config Registers, PW0016A (TSSOP-16)", 5V Tolerant I/O=Yes, Manufacturer="Texas Instruments", Max Frequency(kHz)=400, Operating Temperature Range="-40 to 85 C", Rating=Catalog
Y1: library part CMP-0079303-1, "Crystal, 32.768 KHz, 20 ppm, 7 pF, SMD", Frequency_Fixed=32.768kHz, Frequency Stability="20 ppm", Load Capacitance="7 pF", Manufacturer=Epson, Supplier Part Number 1=732-FC135-32.76KAAG0
ZZ1: library part CMP-0003616-3
ZZ2: library part CMP-0077236-1
ZZ3: library part CMP-0077237-1
ZZ4: library part CMP-0077238-1

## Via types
v1: diameter 30, hole 12, Top Layer to Bottom Layer, 73 vias
v2: diameter 19.68, hole 7.87, Top Layer to Bottom Layer, 21 vias

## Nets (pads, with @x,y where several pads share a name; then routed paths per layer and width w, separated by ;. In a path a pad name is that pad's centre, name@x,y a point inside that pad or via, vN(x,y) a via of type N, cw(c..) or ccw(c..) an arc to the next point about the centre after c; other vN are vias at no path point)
3.3V_ISO: J10.2 J11.1 | length 190
  Top Layer w50: J10.2@1010,2500 J11.1@1200,2500
DVCC: C3.2 C5.2 C6.2 C7.2 C9.2 C10.2 J2.2 J8.6 J8.10 J9.4 J10.1 J15.1 J16.1 R2.1 R3.1 R4.2 R5.2 R6.2 R8.1 R9.2 R10.2 R11.2 R12.1 U1.6 U1.10 U1.28 U2.1 U3.16 | length 1806.1
  Top Layer w7: C9.2@1110.32,587.87 U2.1@1228.35,587.87
  Top Layer w8: R9.2@1029.69,590 C9.2@1107.56,590 ; C9.2@1110,587.56 v1(1110,640) ; C7.2@1675.59,1273.46 1675.59,1315.59 1685.59,1325.59 1745.59,1325.59 1765.75,1345.75 U1.6@1765.75,1461.73 ; U1.28@1824.8,1729.45 1824.8,1774.8 1855.59,1805.59 1905.59,1805.59 1915.59,1815.59 C5.2@1915.59,1848.03 1963.03,1848.03 1975,1860 v1(1975,1885) ; U1.10@1844.49,1461.73 1844.49,1346.69 1865.59,1325.59 1905.59,1325.59 1915.59,1315.59 C6.2@1915.59,1273.46
  Top Layer w15: v1(485,615) R10.2@535.31,615 ; U3.16@892.2,669.57 892.2,724.65 C10.2@897.56,730 v1(950,730) ; v1(1060,460) R12.1@1100,459.68 ; v1@1420.59,1575.59 R8.1@1465.91,1575.59 ; v1(1625,1275) 1674.05,1275 C7.2@1675.59,1273.46 ; v1@1765.59,1929.41 R6.2@1765.59,1885.28 R5.2@1805.59,1885.28 ; C6.2@1917.13,1275 v1(1970,1275) ; R2.1@2830.32,1350 2805,1375.32 v1(2805,1400) 2805,1424.68 R3.1@2830.32,1450 ; v1(2895,2000) R4.2@2940.31,2000 ; v1(2895,2400) R11.2@2940.31,2400
  Top Layer w40: C3.2@779.53,2500 J10.1@910,2500
  other v1: 1420,1575 1765,1930
GND_ISO: C1.1 C2.1 C3.1 C4.1 C5.1 C6.1 C7.1 C8.2 C9.1 C10.1 D1.2 J1.9 J4.5 J5.3 J6.3 J8.9 J8.11 J9.3 J11.6 J11.12 J12.6 J15.3 J16.3 J17.1 J17.6 J17.12 J18.1 J18.6 J18.12 R7.2 U1.9 U1.11 U1.27 U1.49 U2.6 U3.8 | length 1567.6
  Top Layer w7: U2.6@1273.62,572.13 1297.87,572.13 v1(1330,540)
  Top Layer w8: v1(1060,530) C9.1@1107.56,530 ; U1.9@1824.8,1461.73 U1.49@1824.8,1546.38 ; U1.27@1844.49,1729.45 1844.49,1664.49 v2(1825.2,1645.2) v2(1775.59,1595.59) U1.49@1824.8,1546.38 ; U1.11@1864.17,1461.73 1864.17,1507.01 U1.49@1824.8,1546.38
  Top Layer w15: D1.2@400,1549.53 v1(400,1620) ; v1(600,480) U3.8@653.62,490.43 ; U3.8@667.8,490.43 734.57,490.43 770,455 770,190 v1(790,170) ; v1(795,730) C10.1@842.44,730 ; v1@1405.59,1525.59 C8.2@1458.03,1525.59 ; v1@1675.59,1170.59 C7.1@1675.59,1218.03 ; v1(1745,1100) C1.1@1745,1150.32 ; v1(1845,1100) C2.1@1845,1150.32 ; v1@1915.59,1170.59 C6.1@1915.59,1218.03 ; C5.1@1915.59,1903.15 v1@1915.59,1949.41 ; C4.1@2013.15,1365.59 v1@2064.41,1365.59 ; R7.2@2035.28,1755.59 v1@2079.41,1755.59
  Top Layer w30: v1(660,2500) C3.1@720.47,2500
  other v1: 2000,250 2200,250 3050,440 1750,550 1130,700 950,850 625,1000 2900,1000 1350,1100 2900,1150 1675,1170 1915,1170 795,1250 2065,1365 1250,1500 1405,1525 2850,1600 660,1730 820,1730 2650,1750 2080,1755 100,1850 1915,1950 100,2100 660,2100 820,2100 1250,2100 1550,2100 2700,2250 1055,2295 100,2350 2700,2500 100,2600 2900,2600 3400,2600
  other v2: 1725.98,1504.06 1775.59,1504.06 1825.2,1504.06 1684.06,1545.98 1725.98,1545.98 1775.59,1545.98 1825.2,1545.98 1867.13,1545.98 1684.06,1595.59 1725.98,1595.59 1825.2,1595.59 1867.13,1595.59 1684.06,1645.2 1725.98,1645.2 1775.59,1645.2 1867.13,1645.2 1725.98,1687.13 1775.59,1687.13 1825.2,1687.13
NetC1_2: C1.2 U1.7 Y1.1 | length 286.5
  Top Layer w8: Y1.1@1746.38,1255.91 1746.38,1276.38 1785.43,1315.43 U1.7@1785.43,1461.73
  Top Layer w15: C1.2@1745,1189.69 Y1.1@1745,1254.21
NetC2_2: C2.2 U1.8 Y1.2 | length 288
  Top Layer w8: U1.8@1805.12,1461.73 1805.12,1316.06 1844.8,1276.38 Y1.2@1844.8,1255.91
  Top Layer w15: C2.2@1845,1189.69 Y1.2@1845,1255.39
NetC4_2: C4.2 U1.12 | length 163.4
  Top Layer w8: U1.12@1883.86,1461.73 1883.86,1377.32 1895.59,1365.59 C4.2@1958.03,1365.59
NetD1_1: D1.1 R1.2 | length 50.8
  Top Layer w15: R1.2@400,1439.69 D1.1@400,1490.47
NetJ1_2: J1.2 J2.1 | length 764.9
  Bottom Layer w8: J1.2@2900,200 2970,200 3000,230 3000,770 3030,800 J2.1@3100,800
NetJ1_4: J1.4 J2.3 | length 861.9
  Bottom Layer w8: J1.4@2800,200 2800,130 2830,100 3065,100 3100,135 J2.3@3100,600
NetJ3_1: J3.1 U1.37 | length 909.7
  Top Layer w8: J3.1@1055.59,2145.59 1145.59,2145.59 1175.59,2115.59 1175.59,1875.59 1335.59,1715.59 1565.59,1715.59 1577.32,1703.86 U1.37@1641.73,1703.86
NetJ4_6: J4.6 R3.2 | length 251
  Top Layer w8: R3.2@2869.69,1450 3050,1450 J4.6@3100,1400
NetJ4_8: J4.8 R2.2 | length 251
  Top Layer w8: R2.2@2869.69,1350 3050,1350 J4.8@3100,1300
NetJ5_1: J5.1 R11.1 | length 120.3
  Top Layer w15: R11.1@2979.68,2400 J5.1@3100,2400
NetJ6_1: J6.1 R4.1 | length 120.3
  Top Layer w15: R4.1@2979.68,2000 J6.1@3100,2000
NetJ8_2: J8.2 U1.2 | length 765.1
  Top Layer w8: J8.2@1305.59,895.59 1305.59,1115.59 1595.59,1405.59 1665.59,1405.59 1687.01,1427.01 U1.2@1687.01,1461.73
NetJ8_3: J8.3 U1.3 | length 737.7
  Top Layer w8: J8.3@1405.59,895.59 1405.59,1185.59 1605.59,1385.59 1685.59,1385.59 1706.69,1406.69 U1.3@1706.69,1461.73
NetJ8_5: J8.5 U1.5 | length 724.8
  Top Layer w8: J8.5@1605.59,895.59 1555,946.18 1555,1275 1625.59,1345.59 1725.59,1345.59 1746.06,1366.06 U1.5@1746.06,1461.73
NetJ9_8: J9.8 U1.32 | length 624.3
  Top Layer w8: J9.8@1605.59,2295.59 1605.59,1945.59 1746.06,1805.12 U1.32@1746.06,1729.45
NetJ9_12: J9.12 U1.36 | length 956.6
  Top Layer w8: J9.12@1205.59,2295.59 1205.59,1885.59 1305.59,1785.59 1645.59,1785.59 1667.32,1763.86 U1.36@1667.32,1729.45
NetJ12_1: J12.1 R9.1 U3.13 | length 823.4
  Top Layer w7: R9.1@988.19,587.87 R9.1@990,589.68
  Top Layer w8: U3.13@892.2,592.8 987.52,592.8 R9.1@990.32,590 990.32,490.32 v1(950,450)
  Bottom Layer w8: v1(950,450) 950,260 960,250 1250,250 J12.1@1300,300
NetJ12_3: J12.3 U2.9 | length 556.5
  Top Layer w7: U2.9@1250,611.5 v1(1250,670)
  Bottom Layer w8: J12.3@1200,300 1120,380 1120,561.3 1150,591.3 1150,640 1180,670 v1(1250,670)
NetJ12_4: J12.4 U2.3 | length 404.1
  Top Layer w7: J12.4@1200,200 1150,250 1150,390 1234.25,474.25 U2.3@1234.25,548.5
NetJ12_5: J12.5 R12.2 | length 118.3
  Top Layer w15: J12.5@1100,300 R12.2@1100,418.35
NetJ15_2: J15.2 U3.1 | length 665.8
  Top Layer w7: J15.2@400,1100 510,1100 530,1080 530,705 565.43,669.57 U3.1@667.8,669.57
NetJ16_2: J16.2 U3.2 | length 291
  Top Layer w7: J16.2@400,700 485,700 541.02,643.98 U3.2@667.8,643.98
NetR10_1: R10.1 U3.3 | length 89.7
  Top Layer w7: R10.1@578.07,618.39 U3.3@667.8,618.39
"P1.0 INT": J7.1 J11.4 U1.13 | length 3669.3
  Top Layer w8: J11.4@1500,2500 1500,2580 1520,2600 2570,2600 2600,2570 v1(2600,1900) ; U1.13@1909.45,1487.32 2053.86,1487.32 2335.59,1205.59 2335.59,1065.59 2355.59,1045.59 2580.59,1045.59 2600,1065 v1(2600,1800)
  Bottom Layer w8: v1(2600,1800) v1(2600,1900)
P1.1/TA0.0: J4.1 J7.2 U1.14 | length 1638.9
  Top Layer w8: U1.14@1909.45,1507.01 2064.17,1507.01 2355.59,1215.59 2355.59,1165.59 2375.59,1145.59 J7.2@2455.59,1145.59
  Signal Layer 2 w8: J7.2@2455.59,1145.59 2774.84,1145.59 2870,1240.75 2870,1550 2920,1600 J4.1@3000,1600
P1.2/TA0.1: J4.3 J7.3 U1.15 | length 1850.4
  Top Layer w8: U1.15@1909.45,1526.69 2074.49,1526.69 2355.59,1245.59 J7.3@2455.59,1245.59
  Signal Layer 2 w8: J7.3@2455.59,1245.59 2370.59,1245.59 2350,1225 2350,1120 2375,1095 2765,1095 2900,1230 2900,1470 2930,1500 J4.3@3000,1500
"P1.3 OC ALERT": J7.4 J11.8 J13.4 U1.16 | length 5461.4
  Top Layer w8: U1.16@1909.45,1546.38 2084.8,1546.38 2285.59,1345.59 J7.4@2455.59,1345.59
  Bottom Layer w8: J13.4@600,200 600,160 635,125 1345,125 1380,160 1380,380 1650,650 2500,650 2550,700 2550,1320 2524.41,1345.59 J7.4@2455.59,1345.59 2345,1345.59 2325,1365.59 2325,2200 2370,2245 2370,2360 2355,2375 1930,2375 1900,2405 J11.8@1900,2500
"P1.4 OSS": J7.5 J11.2 U1.17 | length 2907.1
  Top Layer w8: U1.17@1909.45,1566.06 2095.12,1566.06 2215.59,1445.59 J7.5@2455.59,1445.59
  Signal Layer 2 w8: J11.2@1300,2500 1300,2420 1320,2400 2495,2400 2525,2370 2525,1460 2510.59,1445.59 J7.5@2455.59,1445.59
"P1.5 PG1": J7.6 J11.9 J13.8 U1.18 | length 5694.5
  Top Layer w8: U1.18@1909.45,1585.75 2105.43,1585.75 2145.59,1545.59 J7.6@2455.59,1545.59
  Bottom Layer w8: J13.8@400,200 400,120 420,100 1390,100 1420,130 1420,370 1650,600 2580,600 2600,620 2600,1510 2564.41,1545.59 J7.6@2455.59,1545.59 2374.41,1545.59 2350,1570 2350,2180 2405,2235 2405,2375 2380,2400 2035,2400 2000,2435 J11.9@2000,2500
